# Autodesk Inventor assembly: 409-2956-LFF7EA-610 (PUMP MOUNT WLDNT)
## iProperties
Created: 2011-01
Part Number: 409-2956-LFF7EA-610 (PUMP MOUNT WLDNT)
Document SubType Name: Weldment
Designer: S. Boerckel
Weld Material: Welded Aluminum-6061
Mass: 21556.4 g
Surface Area: 5152.44 cm^2
Volume: 2742.54 cm^3
Density: 7.86 g/cm^3
Author: S. Boerckel
Revision Number: 0
Material: WELDMENT
SMR: =<MATERIAL>
